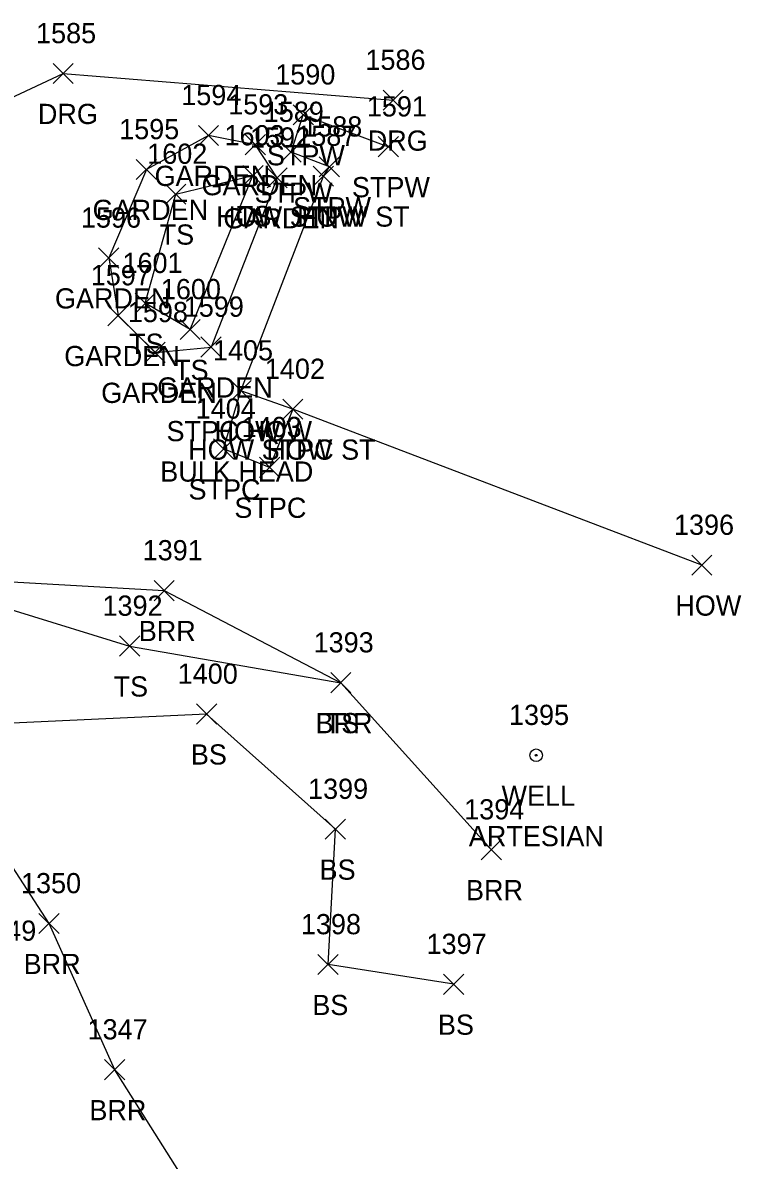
# Model space of a CAD drawing. Extents: x 1654425 to 1656893, y 667839 to 678429.
# Drawn here: x 1654688.3 to 1654759.4, y 668502.8 to 668615.4 of the extents above; entities that cross this region are included whole.
import ezdxf

# ---------------------------------------------------------------- set-up
doc = ezdxf.new("R2010")
doc.units = 0
for name, color, linetype in [('L_A', 7, 'Continuous'), ('L_C', 7, 'Continuous'), ('L_I', 7, 'Continuous'), ('L_TIC', 7, 'Continuous'), ('LABL', 7, 'Continuous'), ('LAPB', 7, 'Continuous'), ('LBC', 7, 'Continuous'), ('LBF', 7, 'Continuous'), ('LELB', 7, 'Continuous'), ('R_A', 7, 'Continuous'), ('R_I', 7, 'Continuous'), ('R_TIC', 7, 'Continuous'), ('RDG', 7, 'Continuous'), ('U_A', 7, 'Continuous'), ('U_C', 7, 'Continuous'), ('U_I', 7, 'Continuous'), ('UWW', 7, 'Continuous')]:
    doc.layers.add(name, color=color, linetype=linetype)

msp = doc.modelspace()

# ---------------------------------------------------------------- linework, layer by layer
at = {"layer": 'L_TIC'}
for points in [[(1654715.07, 668605.31), (1654717.07, 668607.31)], [(1654717.07, 668605.31), (1654715.07, 668607.31)], [(1654705.68, 668603.27), (1654707.68, 668605.27)], [(1654707.68, 668603.27), (1654705.68, 668605.27)], [(1654710.32, 668602.35), (1654712.32, 668604.35)], [(1654712.32, 668602.35), (1654710.32, 668604.35)], [(1654723.49, 668602.15), (1654725.49, 668604.15)], [(1654725.49, 668602.15), (1654723.49, 668604.15)], [(1654713.85, 668601.61), (1654715.85, 668603.61)], [(1654715.85, 668601.61), (1654713.85, 668603.61)], [(1654699.53, 668599.9), (1654701.53, 668601.9)], [(1654701.53, 668599.9), (1654699.53, 668601.9)], [(1654717.65, 668600.16), (1654719.65, 668602.16)], [(1654719.65, 668600.16), (1654717.65, 668602.16)], [(1654710.08, 668599.29), (1654712.08, 668601.29)], [(1654712.08, 668599.29), (1654710.08, 668601.29)], [(1654710.08, 668599.29), (1654712.08, 668601.29)], [(1654712.08, 668599.29), (1654710.08, 668601.29)], [(1654712.48, 668599.07), (1654714.48, 668601.07)], [(1654714.48, 668599.07), (1654712.48, 668601.07)], [(1654712.48, 668599.07), (1654714.48, 668601.07)], [(1654714.48, 668599.07), (1654712.48, 668601.07)], [(1654717.06, 668599.24), (1654719.06, 668601.24)], [(1654719.06, 668599.24), (1654717.06, 668601.24)], [(1654717.06, 668599.24), (1654719.06, 668601.24)], [(1654719.06, 668599.24), (1654717.06, 668601.24)], [(1654702.43, 668597.46), (1654704.43, 668599.46)], [(1654704.43, 668597.46), (1654702.43, 668599.46)], [(1654695.8, 668591.14), (1654697.8, 668593.14)], [(1654697.8, 668591.14), (1654695.8, 668593.14)], [(1654699.41, 668586.65), (1654701.41, 668588.65)], [(1654701.41, 668586.65), (1654699.41, 668588.65)], [(1654696.72, 668585.43), (1654698.72, 668587.43)], [(1654698.72, 668585.43), (1654696.72, 668587.43)], [(1654703.86, 668584.06), (1654705.86, 668586.06)], [(1654705.86, 668584.06), (1654703.86, 668586.06)], [(1654703.86, 668584.06), (1654705.86, 668586.06)], [(1654705.86, 668584.06), (1654703.86, 668586.06)], [(1654705.93, 668582.32), (1654707.93, 668584.32)], [(1654707.93, 668582.32), (1654705.93, 668584.32)], [(1654705.93, 668582.32), (1654707.93, 668584.32)], [(1654707.93, 668582.32), (1654705.93, 668584.32)], [(1654700.39, 668581.79), (1654702.39, 668583.79)], [(1654702.39, 668581.79), (1654700.39, 668583.79)], [(1654708.89, 668578), (1654710.89, 668580)], [(1654710.89, 668578), (1654708.89, 668580)], [(1654708.89, 668578), (1654710.89, 668580)], [(1654710.89, 668578), (1654708.89, 668580)], [(1654714.03, 668576.17), (1654716.03, 668578.17)], [(1654716.03, 668576.17), (1654714.03, 668578.17)], [(1654714.03, 668576.17), (1654716.03, 668578.17)], [(1654716.03, 668576.17), (1654714.03, 668578.17)], [(1654707.18, 668572.23), (1654709.18, 668574.23)], [(1654709.18, 668572.23), (1654707.18, 668574.23)], [(1654711.73, 668570.41), (1654713.73, 668572.41)], [(1654713.73, 668570.41), (1654711.73, 668572.41)], [(1654754.53, 668560.73), (1654756.53, 668562.73)], [(1654756.53, 668560.73), (1654754.53, 668562.73)], [(1654701.29, 668558.21), (1654703.29, 668560.21)], [(1654703.29, 668558.21), (1654701.29, 668560.21)], [(1654697.87, 668552.72), (1654699.87, 668554.72)], [(1654699.87, 668552.72), (1654697.87, 668554.72)], [(1654718.79, 668549.09), (1654720.79, 668551.09)], [(1654720.79, 668549.09), (1654718.79, 668551.09)], [(1654718.79, 668549.09), (1654720.79, 668551.09)], [(1654720.79, 668549.09), (1654718.79, 668551.09)], [(1654705.49, 668545.99), (1654707.49, 668547.99)], [(1654707.49, 668545.99), (1654705.49, 668547.99)], [(1654718.24, 668534.59), (1654720.24, 668536.59)], [(1654720.24, 668534.59), (1654718.24, 668536.59)], [(1654733.69, 668532.56), (1654735.69, 668534.56)], [(1654735.69, 668532.56), (1654733.69, 668534.56)], [(1654689.89, 668525.25), (1654691.89, 668527.25)], [(1654691.89, 668525.25), (1654689.89, 668527.25)], [(1654717.52, 668521.19), (1654719.52, 668523.19)], [(1654719.52, 668521.19), (1654717.52, 668523.19)], [(1654729.96, 668519.24), (1654731.96, 668521.24)], [(1654731.96, 668519.24), (1654729.96, 668521.24)], [(1654696.39, 668510.78), (1654698.39, 668512.78)], [(1654698.39, 668510.78), (1654696.39, 668512.78)]]:
    msp.add_lwpolyline(points, dxfattribs=at)
at = {"layer": 'LABL'}
msp.add_lwpolyline([(1654727.47, 668448.66), (1654723.77, 668470.01), (1654697.39, 668511.78), (1654690.89, 668526.25), (1654681.79, 668540.29), (1654676.53, 668550.52), (1654673.89, 668561.81), (1654676.18, 668560.69), (1654702.29, 668559.21), (1654719.79, 668550.09), (1654734.69, 668533.56)], dxfattribs=at)
at = {"layer": 'LAPB'}
for points in [[(1654713.48, 668600.07), (1654711.32, 668603.35), (1654706.68, 668604.27), (1654700.53, 668600.9), (1654696.8, 668592.14), (1654697.72, 668586.43), (1654701.39, 668582.79), (1654706.93, 668583.32)], [(1654713.48, 668600.07), (1654706.93, 668583.32)]]:
    msp.add_lwpolyline(points, dxfattribs=at)
at = {"layer": 'LBC'}
msp.add_lwpolyline([(1654755.53, 668561.73), (1654715.03, 668577.17), (1654709.89, 668579), (1654718.06, 668600.24)], dxfattribs=at)
at = {"layer": 'LBF'}
for points in [[(1654718.06, 668600.24), (1654718.65, 668601.16), (1654714.85, 668602.61), (1654716.07, 668606.31), (1654724.49, 668603.15)], [(1654715.03, 668577.17), (1654712.73, 668571.41), (1654708.18, 668573.23), (1654709.89, 668579)]]:
    msp.add_lwpolyline(points, dxfattribs=at)
at = {"layer": 'LELB'}
for points in [[(1654704.86, 668585.06), (1654700.41, 668587.65), (1654703.43, 668598.46), (1654711.08, 668600.29)], [(1654704.86, 668585.06), (1654711.08, 668600.29)], [(1654676.18, 668560.69), (1654698.87, 668553.72), (1654719.79, 668550.09)], [(1654730.96, 668520.24), (1654718.52, 668522.19), (1654719.24, 668535.59), (1654706.49, 668546.99), (1654682.94, 668545.89)]]:
    msp.add_lwpolyline(points, dxfattribs=at)
at = {"layer": 'R_TIC'}
for points in [[(1654691.29, 668609.4), (1654693.29, 668611.4)], [(1654693.29, 668609.4), (1654691.29, 668611.4)], [(1654723.97, 668606.76), (1654725.97, 668608.76)], [(1654725.97, 668606.76), (1654723.97, 668608.76)]]:
    msp.add_lwpolyline(points, dxfattribs=at)
at = {"layer": 'RDG'}
msp.add_lwpolyline([(1654672.51, 668598), (1654681.14, 668605.18), (1654692.29, 668610.4), (1654724.97, 668607.76)], dxfattribs=at)
at = {"layer": 'UWW'}
for radius in [0.625, 0.0833]:
    msp.add_circle((1654739.13, 668542.91), radius, dxfattribs=at)

# ---------------------------------------------------------------- texts
at = {"layer": 'L_A'}
for s, p in [('STPW', (1654712.46, 668601.31)), ('GARDEN', (1654701.34, 668599.27)), ('GARDEN', (1654705.99, 668598.35)), ('STPW', (1654711.24, 668597.61)), ('STPW', (1654720.88, 668598.15)), ('GARDEN', (1654695.2, 668595.9)), ('STPW', (1654715.05, 668596.16)), ('HOW STPW ST', (1654707.44, 668595.24)), ('GARDEN', (1654708.15, 668595.07)), ('GARDEN', (1654708.15, 668595.07)), ('TS', (1654709.49, 668595.29)), ('TS', (1654709.49, 668595.29)), ('HOW', (1654715.45, 668595.24)), ('TS', (1654701.84, 668593.46)), ('GARDEN', (1654691.47, 668587.14)), ('TS', (1654698.82, 668582.65)), ('GARDEN', (1654692.39, 668581.43)), ('TS', (1654703.27, 668580.06)), ('TS', (1654703.27, 668580.06)), ('GARDEN', (1654696.05, 668577.79)), ('GARDEN', (1654701.6, 668578.32)), ('GARDEN', (1654701.6, 668578.32)), ('STPC HOW', (1654702.52, 668574)), ('HOW', (1654707.28, 668574)), ('HOW STPC ST', (1654704.66, 668572.17)), ('HOW', (1654712.41, 668572.17)), ('STPC', (1654704.7, 668568.23)), ('STPC', (1654709.24, 668566.41)), ('HOW', (1654752.91, 668556.73)), ('BRR', (1654699.77, 668554.21)), ('TS', (1654697.28, 668548.72)), ('BRR', (1654717.27, 668545.09)), ('TS', (1654718.19, 668545.09)), ('BS', (1654704.93, 668541.99)), ('BS', (1654717.68, 668530.59)), ('BRR', (1654732.18, 668528.56)), ('BRR', (1654688.37, 668521.25)), ('BS', (1654716.96, 668517.19)), ('BS', (1654729.4, 668515.24)), ('BRR', (1654694.88, 668506.78))]:
    msp.add_text(s, height=2, dxfattribs=at).set_placement(p)
at = {"layer": 'L_C'}
msp.add_text('BULK HEAD', height=2, dxfattribs=at).set_placement((1654701.9, 668570))
at = {"layer": 'L_I'}
for s, p in [('1590', (1654713.29, 668609.31)), ('1594', (1654703.98, 668607.27)), ('1593', (1654708.63, 668606.35)), ('1589', (1654712.15, 668605.61)), ('1591', (1654722.36, 668606.15)), ('1595', (1654697.83, 668603.9)), ('1603', (1654708.26, 668603.29)), ('1603', (1654708.26, 668603.29)), ('1587', (1654715.37, 668603.24)), ('1587', (1654715.37, 668603.24)), ('1588', (1654715.96, 668604.16)), ('1592', (1654710.79, 668603.07)), ('1592', (1654710.79, 668603.07)), ('1602', (1654700.61, 668601.46)), ('1596', (1654694.05, 668595.14)), ('1601', (1654698.16, 668590.65)), ('1597', (1654695.02, 668589.43)), ('1600', (1654701.96, 668588.06)), ('1600', (1654701.96, 668588.06)), ('1599', (1654704.23, 668586.32)), ('1599', (1654704.23, 668586.32)), ('1598', (1654698.69, 668585.79)), ('1405', (1654707.12, 668582)), ('1405', (1654707.12, 668582)), ('1402', (1654712.26, 668580.17)), ('1402', (1654712.26, 668580.17)), ('1404', (1654705.41, 668576.23)), ('1403', (1654709.96, 668574.41)), ('1396', (1654752.78, 668564.73)), ('1391', (1654700.16, 668562.21)), ('1392', (1654696.18, 668556.72)), ('1393', (1654717.09, 668553.09)), ('1393', (1654717.09, 668553.09)), ('1400', (1654703.63, 668549.99)), ('1399', (1654716.54, 668538.59)), ('1394', (1654732, 668536.56)), ('1350', (1654688.11, 668529.25)), ('1349', (1654683.67, 668524.55)), ('1398', (1654715.83, 668525.19)), ('1397', (1654728.27, 668523.24)), ('1347', (1654694.7, 668514.78))]:
    msp.add_text(s, height=2, dxfattribs=at).set_placement(p)
at = {"layer": 'R_A'}
for p in [(1654689.78, 668605.4), (1654722.45, 668602.76)]:
    msp.add_text('DRG', height=2, dxfattribs=at).set_placement(p)
at = {"layer": 'R_I'}
for s, p in [('1585', (1654689.6, 668613.4)), ('1586', (1654722.22, 668610.76))]:
    msp.add_text(s, height=2, dxfattribs=at).set_placement(p)
at = {"layer": 'U_A'}
msp.add_text('WELL', height=2, dxfattribs=at).set_placement((1654735.7, 668537.91))
at = {"layer": 'U_C'}
msp.add_text('ARTESIAN', height=2, dxfattribs=at).set_placement((1654732.46, 668533.91))
at = {"layer": 'U_I'}
msp.add_text('1395', height=2, dxfattribs=at).set_placement((1654736.44, 668545.91))

doc.saveas('drawing.dxf')
